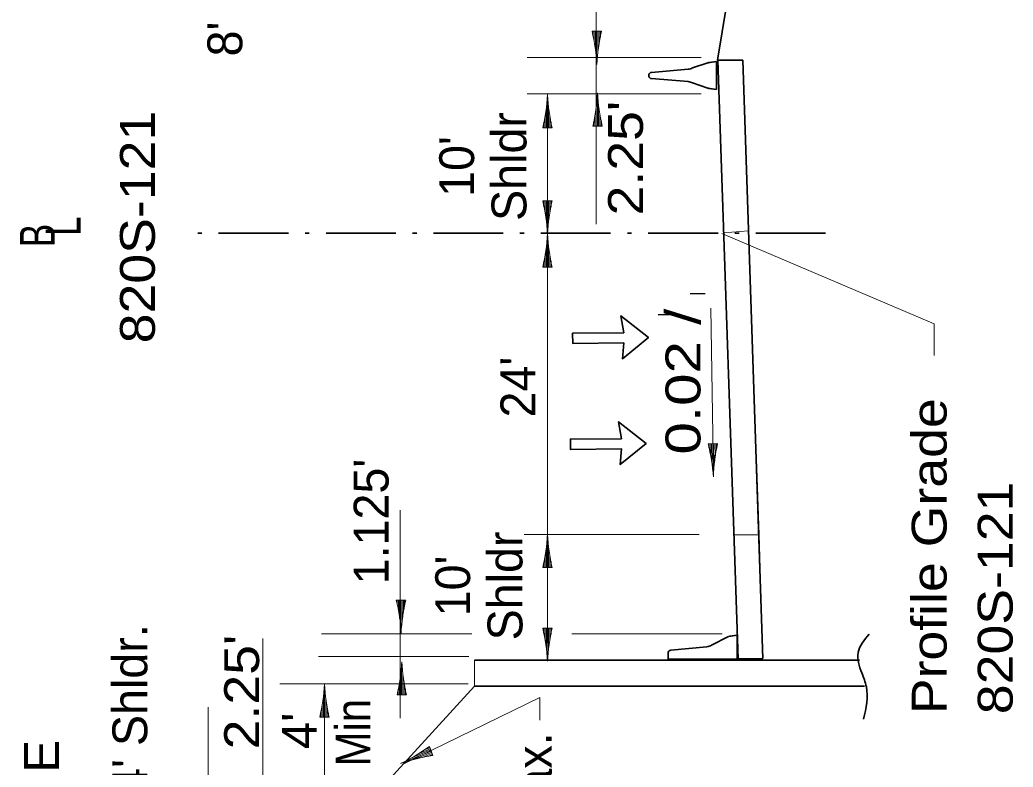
# Model space of a CAD drawing. Extents: x 2363427 to 2368559, y 6957299 to 6980140.
# Drawn here: x 2365076.8 to 2365475.6, y 6964957.4 to 6965257.3 of the extents above; entities that cross this region are included whole.
import ezdxf
from ezdxf.enums import TextEntityAlignment as Align

# ---------------------------------------------------------------- set-up
doc = ezdxf.new("R2010")
doc.units = 0
doc.header["$LTSCALE"] = 5.6
doc.linetypes.add('DOT_DASHED', pattern=[7.7, 5, -1.2, 0.3, -1.2])
doc.layers.add('3', color=7, linetype='Continuous', lineweight=35)
doc.layers.add('4', color=7, linetype='Continuous', lineweight=13)

msp = doc.modelspace()

# ---------------------------------------------------------------- linework, layer by layer
at = {"layer": '3'}
for p, q in [((2365353.153, 6965240.114), (2365353.163, 6965240.138)), ((2365356.427, 6965240.626), (2365353.163, 6965240.138)), ((2365356.427, 6965240.626), (2365353.361, 6965240.168)), ((2365356.427, 6965240.626), (2365356.427, 6965235.002)), ((2365366.994, 6965241.114), (2365375.115, 6965000.972)), ((2365345.087, 6965237.478), (2365330.383, 6965236.243)), ((2365346.875, 6965238.007), (2365352.989, 6965240.048)), ((2365329.357, 6965235.402), (2365329.357, 6965235.002)), ((2365329.357, 6965234.601), (2365329.357, 6965235.002)), ((2365345.087, 6965232.525), (2365330.383, 6965233.76)), ((2365356.427, 6965229.376), (2365356.427, 6965235.002)), ((2365346.875, 6965231.996), (2365352.989, 6965229.954)), ((2365353.153, 6965229.89), (2365353.163, 6965229.864)), ((2365356.427, 6965229.376), (2365353.163, 6965229.864)), ((2365356.427, 6965229.376), (2365353.361, 6965229.836)), ((2365319.275, 6965127.64), (2365298.77, 6965127.444)), ((2365318.36, 6965085.124), (2365297.855, 6965084.928)), ((2365354.451, 6965006.274), (2365361.285, 6965009.788)), ((2365361.453, 6965009.854), (2365361.463, 6965009.88)), ((2365364.751, 6965010.372), (2365364.751, 6965000.742)), ((2365338.137, 6965004.278), (2365352.62, 6965005.732)), ((2365337.031, 6965000.742), (2365337.031, 6965003.056)), ((2365259.361, 6965000.314), (2365413.871, 6965000.314)), ((2365364.751, 6965000.742), (2365337.031, 6965000.742)), ((2365365.116, 6965000.802), (2365375.12, 6965000.802)), ((2365259.357, 6964989.862), (2365215.222, 6964941.608)), ((2365292.399, 6964989.858), (2365259.361, 6964989.858)), ((2365292.399, 6964989.858), (2365415.839, 6964989.858))]:
    msp.add_line(p, q, dxfattribs=at)
at = {"layer": '3', "linetype": 'DOT_DASHED'}
msp.add_line((2365400.238, 6965171.648), (2365144.542, 6965171.648), dxfattribs=at)
at = {"layer": '3', "lineweight": 13}
for p, q in [((2365443.852, 6965135.264), (2365358.571, 6965171.542)), ((2365443.852, 6965122.568), (2365443.852, 6965135.264)), ((2365174.345, 6964906.409), (2365174.345, 6965009.032)), ((2365258.238, 6965010.934), (2365197.935, 6965010.934)), ((2365358.733, 6965010.934), (2365298.43, 6965010.934)), ((2365257.019, 6965001.8), (2365196.717, 6965001.8)), ((2365259.361, 6964989.858), (2365259.361, 6965000.314)), ((2365199.111, 6964942.054), (2365199.111, 6964990.853)), ((2365285.555, 6964985.333), (2365231.259, 6964958.832)), ((2365285.555, 6964985.333), (2365285.555, 6964976.2)), ((2365152.449, 6964766.446), (2365152.449, 6964981.39))]:
    msp.add_line(p, q, dxfattribs=at)
at = {"layer": '3'}
for points in [[(2365356.876, 6965241.104), (2365364.429, 6965286.806), (2365354.106, 6965326.882)], [(2365366.993, 6965241.114), (2365356.988, 6965241.114), (2365365.116, 6965000.802)], [(2365319.275, 6965127.64), (2365318.743, 6965121.324), (2365329.13, 6965129.86), (2365318.03, 6965138.462), (2365319.238, 6965131.734)], [(2365319.238, 6965131.734), (2365298.733, 6965131.54), (2365298.77, 6965127.444)], [(2365318.36, 6965085.124), (2365317.828, 6965078.808), (2365328.215, 6965087.344), (2365317.115, 6965095.946), (2365318.323, 6965089.218)], [(2365318.323, 6965089.218), (2365297.818, 6965089.024), (2365297.855, 6965084.928)], [(2365361.665, 6965009.91), (2365364.805, 6965010.38), (2365361.463, 6965009.88)]]:
    msp.add_lwpolyline(points, dxfattribs=at)
at = {"layer": '3', "lineweight": 13}
for points in [[(2365359.234, 6965171.891), (2365369.342, 6965172.612), (2365366.994, 6965241.114), (2365356.988, 6965241.114)], [(2365363.566, 6965050.676), (2365373.674, 6965050.676), (2365369.342, 6965172.612), (2365359.234, 6965171.891)], [(2365365.116, 6965000.802), (2365375.115, 6965000.972), (2365373.674, 6965050.676), (2365363.566, 6965050.676)]]:
    msp.add_lwpolyline(points, close=True, dxfattribs=at)
at = {"layer": '3'}
for points in [[(2365329.13, 6965129.86), (2365318.743, 6965121.324), (2365319.275, 6965127.64), (2365298.77, 6965127.444), (2365298.733, 6965131.54), (2365319.238, 6965131.734), (2365318.03, 6965138.462)], [(2365328.215, 6965087.344), (2365317.828, 6965078.808), (2365318.36, 6965085.124), (2365297.855, 6965084.928), (2365297.818, 6965089.024), (2365318.323, 6965089.218), (2365317.115, 6965095.946)]]:
    msp.add_lwpolyline(points, close=True, dxfattribs=at)
for centre, radius, start, end in [((2365353.538, 6965238.982), 1.2, 98.51269, 117.22516), ((2365330.504, 6965235.05), 1.2, 95.72178, 162.90786), ((2365344.588, 6965242.454), 5, 275.73538, 297.22872), ((2365330.504, 6965234.955), 1.2, 197.09214, 264.27822), ((2365344.588, 6965227.55), 5, 62.77128, 84.26462), ((2365353.538, 6965231.023), 1.2, 242.77484, 261.48731), ((2365352.109, 6965010.826), 5.12, 275.73538, 297.22872), ((2365338.26, 6965003.057), 1.229, 95.72178, 180)]:
    msp.add_arc(centre, radius, start, end, dxfattribs=at)
msp.add_spline([(2365415.542, 6964976.676), (2365416.654, 6964989.644), (2365414.8, 6964995.202), (2365413.317, 6965003.354), (2365417.766, 6965010.764)], degree=3, dxfattribs=at)
at = {"layer": '4'}
for p, q in [((2365308.128, 6965175.3), (2365308.128, 6965327.142)), ((2365306.517, 6965252.749), (2365310.347, 6965252.749)), ((2365306.867, 6965252.749), (2365306.867, 6965251.164)), ((2365307.367, 6965252.749), (2365307.367, 6965248.473)), ((2365307.867, 6965252.749), (2365307.867, 6965245.399)), ((2365308.367, 6965252.749), (2365308.367, 6965240.185)), ((2365308.867, 6965252.749), (2365308.867, 6965244.14)), ((2365309.367, 6965252.749), (2365309.367, 6965247.887)), ((2365309.867, 6965252.749), (2365309.867, 6965250.368)), ((2365350.295, 6965242.265), (2365280.543, 6965242.265)), ((2365350.295, 6965227.653), (2365280.543, 6965227.653)), ((2365288.573, 6965213.924), (2365288.573, 6965226.488)), ((2365288.638, 6965007.29), (2365288.638, 6965227.653)), ((2365308.672, 6965214.666), (2365308.672, 6965227.23)), ((2365288.073, 6965213.924), (2365288.073, 6965221.274)), ((2365289.073, 6965213.924), (2365289.073, 6965222.533)), ((2365308.172, 6965214.666), (2365308.172, 6965222.016)), ((2365309.172, 6965214.666), (2365309.172, 6965223.274)), ((2365287.573, 6965213.924), (2365287.573, 6965218.2)), ((2365289.573, 6965213.924), (2365289.573, 6965218.786)), ((2365290.073, 6965213.924), (2365290.073, 6965216.305)), ((2365307.172, 6965214.666), (2365307.172, 6965216.25)), ((2365307.672, 6965214.666), (2365307.672, 6965218.942)), ((2365309.672, 6965214.666), (2365309.672, 6965219.528)), ((2365310.172, 6965214.666), (2365310.172, 6965217.046)), ((2365286.723, 6965213.924), (2365290.553, 6965213.924)), ((2365287.073, 6965213.924), (2365287.073, 6965215.509)), ((2365306.822, 6965214.666), (2365310.652, 6965214.666)), ((2365286.723, 6965184.694), (2365290.553, 6965184.694)), ((2365287.073, 6965184.694), (2365287.073, 6965183.11)), ((2365287.573, 6965184.694), (2365287.573, 6965180.418)), ((2365288.073, 6965184.694), (2365288.073, 6965177.344)), ((2365288.573, 6965184.694), (2365288.573, 6965172.13)), ((2365289.073, 6965184.694), (2365289.073, 6965176.086)), ((2365289.573, 6965184.694), (2365289.573, 6965179.832)), ((2365290.073, 6965184.694), (2365290.073, 6965182.314)), ((2365288.573, 6965158.072), (2365288.573, 6965170.636)), ((2365288.073, 6965158.072), (2365288.073, 6965165.422)), ((2365289.073, 6965158.072), (2365289.073, 6965166.682)), ((2365287.573, 6965158.072), (2365287.573, 6965162.348)), ((2365289.573, 6965158.072), (2365289.573, 6965162.934)), ((2365290.073, 6965158.072), (2365290.073, 6965160.454)), ((2365286.723, 6965158.072), (2365290.553, 6965158.072)), ((2365287.073, 6965158.072), (2365287.073, 6965159.658)), ((2365355.222, 6965073.88), (2365354.148, 6965141.596)), ((2365353.096, 6965087.16), (2365356.925, 6965087.22)), ((2365353.446, 6965087.164), (2365353.471, 6965085.58)), ((2365353.946, 6965087.172), (2365354.014, 6965082.896)), ((2365354.446, 6965087.18), (2365354.562, 6965079.832)), ((2365354.946, 6965087.188), (2365355.145, 6965074.626)), ((2365355.446, 6965087.196), (2365355.582, 6965078.588)), ((2365355.945, 6965087.204), (2365356.023, 6965082.344)), ((2365356.445, 6965087.212), (2365356.483, 6965084.832)), ((2365229.559, 6964977.046), (2365229.559, 6965060.458)), ((2365349.459, 6965050.802), (2365279.307, 6965050.802)), ((2365288.573, 6965037.492), (2365288.573, 6965050.056)), ((2365288.073, 6965037.492), (2365288.073, 6965044.842)), ((2365289.073, 6965037.492), (2365289.073, 6965046.1)), ((2365287.573, 6965037.492), (2365287.573, 6965041.768)), ((2365289.573, 6965037.492), (2365289.573, 6965042.354)), ((2365286.723, 6965037.492), (2365290.553, 6965037.492)), ((2365287.073, 6965037.492), (2365287.073, 6965039.076)), ((2365290.073, 6965037.492), (2365290.073, 6965039.872)), ((2365227.949, 6965024.432), (2365231.779, 6965024.432)), ((2365228.299, 6965024.432), (2365228.299, 6965022.847)), ((2365228.799, 6965024.432), (2365228.799, 6965020.156)), ((2365229.299, 6965024.432), (2365229.299, 6965017.082)), ((2365229.799, 6965024.432), (2365229.799, 6965011.868)), ((2365230.299, 6965024.432), (2365230.299, 6965015.823)), ((2365230.799, 6965024.432), (2365230.799, 6965019.57)), ((2365231.299, 6965024.432), (2365231.299, 6965022.051)), ((2365286.723, 6965013.168), (2365290.553, 6965013.168)), ((2365287.073, 6965013.168), (2365287.073, 6965011.584)), ((2365287.573, 6965013.168), (2365287.573, 6965008.892)), ((2365288.073, 6965013.168), (2365288.073, 6965005.818)), ((2365288.573, 6965013.168), (2365288.573, 6965000.604)), ((2365289.073, 6965013.168), (2365289.073, 6965004.56)), ((2365289.573, 6965013.168), (2365289.573, 6965008.306)), ((2365290.073, 6965013.168), (2365290.073, 6965010.788)), ((2365230.103, 6964986.348), (2365230.103, 6964998.912)), ((2365229.603, 6964986.348), (2365229.603, 6964993.698)), ((2365230.603, 6964986.348), (2365230.603, 6964994.958)), ((2365256.772, 6964990.853), (2365181.212, 6964990.853)), ((2365199.189, 6964977.421), (2365199.189, 6964989.985)), ((2365229.103, 6964986.348), (2365229.103, 6964990.624)), ((2365231.103, 6964986.348), (2365231.103, 6964991.21)), ((2365198.689, 6964977.421), (2365198.689, 6964986.031)), ((2365228.253, 6964986.348), (2365232.083, 6964986.348)), ((2365228.603, 6964986.348), (2365228.603, 6964987.934)), ((2365231.603, 6964986.348), (2365231.603, 6964988.73)), ((2365198.189, 6964977.421), (2365198.189, 6964982.283)), ((2365199.689, 6964977.421), (2365199.689, 6964984.771)), ((2365200.189, 6964977.421), (2365200.189, 6964981.698)), ((2365201.039, 6964977.421), (2365197.209, 6964977.421)), ((2365197.689, 6964977.421), (2365197.689, 6964979.803)), ((2365200.689, 6964977.421), (2365200.689, 6964979.006)), ((2365241.4, 6964965.184), (2365239.195, 6964964.286)), ((2365242.663, 6964962.082), (2365241.219, 6964965.628)), ((2365241.965, 6964963.796), (2365230.331, 6964959.054)), ((2365241.777, 6964964.258), (2365233.803, 6964961.01)), ((2365242.155, 6964963.332), (2365235.348, 6964960.559)), ((2365241.589, 6964964.72), (2365237.085, 6964962.886)), ((2365242.343, 6964962.87), (2365238.383, 6964961.255)), ((2365242.531, 6964962.406), (2365241.063, 6964961.808))]:
    msp.add_line(p, q, dxfattribs=at)
at = {"layer": '4', "lineweight": 25}
for p, q in [((2365345.945, 6965147.469), (2365351.944, 6965147.469)), ((2365340.802, 6965138.904), (2365333.088, 6965138.904))]:
    msp.add_line(p, q, dxfattribs=at)
at = {"layer": '4'}
for centre, start, end in [((2365236.309, 6965235.856), 2.84356, 13.52961), ((2365380.556, 6965235.856), 166.47039, 177.15644), ((2365216.515, 6965230.819), 346.47039, 357.15644), ((2365360.762, 6965230.819), 182.84356, 193.52961), ((2365236.614, 6965231.56), 346.47039, 357.15644), ((2365380.861, 6965231.56), 182.84356, 193.52961), ((2365216.515, 6965167.802), 2.84356, 13.52961), ((2365360.762, 6965167.802), 166.47039, 177.15644), ((2365216.515, 6965174.967), 346.47039, 357.15644), ((2365360.762, 6965174.967), 182.84356, 193.52961), ((2365283.165, 6965069.155), 3.7522, 14.43825), ((2365427.394, 6965071.442), 167.37903, 178.06508), ((2365216.515, 6965054.386), 346.47039, 357.15644), ((2365360.762, 6965054.386), 182.84356, 193.52961), ((2365157.741, 6965007.539), 2.84356, 13.52961), ((2365301.988, 6965007.539), 166.47039, 177.15644), ((2365216.515, 6964996.276), 2.84356, 13.52961), ((2365360.762, 6964996.276), 166.47039, 177.15644), ((2365158.045, 6965003.243), 346.47039, 357.15644), ((2365302.292, 6965003.243), 182.84356, 193.52961), ((2365127, 6964994.316), 346.47039, 357.15644), ((2365271.247, 6964994.316), 182.84356, 193.52961), ((2365199.082, 6965024.273), 295.01271, 305.69876), ((2365253.513, 6964890.689), 98.63954, 109.32559)]:
    msp.add_arc(centre, 72.212, start, end, dxfattribs=at)

# ---------------------------------------------------------------- texts
at = {"layer": '3', "width": 0.75}
msp.add_text('B', height=14, rotation=90, dxfattribs=at).set_placement((2365090.843, 6965170.787), align=Align.CENTER)
at = {"layer": '4'}
for s, rotation, p in [("8' Shldr.", 90, (2365166.124, 6965276.694)), ('Shldr', 90, (2365280.189, 6965198.465)), ("10'", 90, (2365259.189, 6965198.464)), ("24' ", 90, (2365283.758, 6965112.523)), ("1.125'", 90, (2365224.842, 6965055.954)), ('Shldr', 90, (2365278.58, 6965030.098)), ("10'", 90, (2365257.58, 6965030.099)), ("4' Shldr.", 90, (2365128.003, 6964980.691)), ('3:1 Max.', 90.562, (2365290.595, 6964935.485))]:
    msp.add_text(s, height=14, rotation=rotation, dxfattribs=at).set_placement(p, align=Align.CENTER)
for s, width, p in [("2.25'", 1.15, (2365326.962, 6965201.821)), ('820S-121', 1.15, (2365131.035, 6965174.168)), ('L', 0.75, (2365101.26, 6965174.512)), ('0.02 /', 1.25, (2365350.022, 6965112.128)), ("2.25'", 1.15, (2365172.871, 6964987.508)), ('Min', 0.9, (2365217.581, 6964971.219)), ("4'", 1.05, (2365196.044, 6964971.936)), ('121 HOV-HE', 1.05, (2365092.551, 6964910.964))]:
    msp.add_text(s, height=14, rotation=90, dxfattribs=dict(at, width=width)).set_placement(p, align=Align.CENTER)
at = {"layer": '4', "width": 1.15}
for s, p in [('Profile Grade ', (2365448.857, 6964978.612)), ('820S-121', (2365475.357, 6964978.612))]:
    msp.add_text(s, height=14, rotation=90, dxfattribs=at).set_placement(p)

doc.saveas('drawing.dxf')
